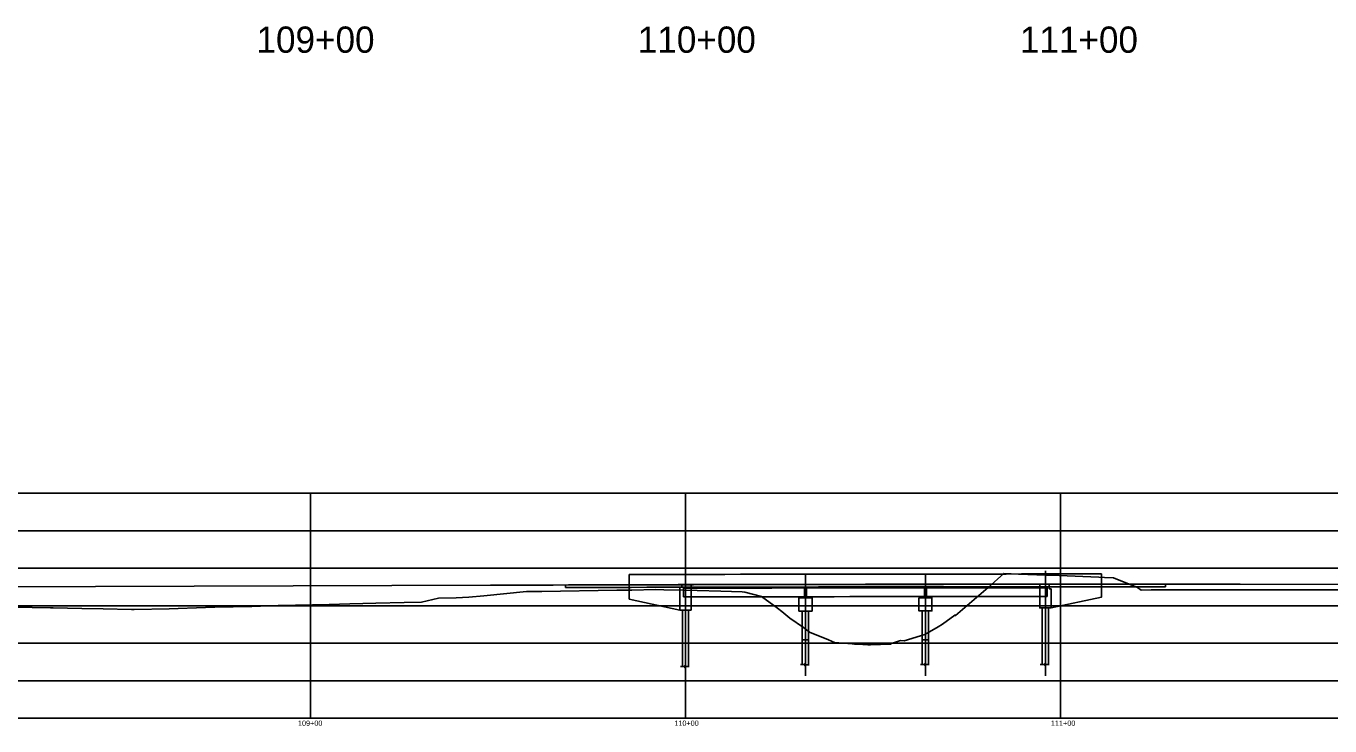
# Model space of a CAD drawing. Extents: x 1932071 to 1934815, y 598385 to 598883.
# Drawn here: x 1933216.8 to 1933564.6, y 598385.1 to 598571.7 of the extents above; entities that cross this region are included whole.
import ezdxf

# ---------------------------------------------------------------- set-up
doc = ezdxf.new("R2010")
doc.units = 0
for name, color, linetype in [('B_Centerline', 7, 'Continuous'), ('B_Concrete', 7, 'Continuous'), ('B_Pr_Abut_Wingwall', 7, 'Continuous'), ('B_Pr_Beam_Line', 7, 'Continuous'), ('B_Pr_Cap_Beams', 7, 'Continuous'), ('B_Pr_Columns', 7, 'Continuous'), ('B_Pr_Deck', 7, 'Continuous'), ('B_Pr_Rail', 7, 'Continuous'), ('BR_Pr_Cap_Beams', 7, 'Continuous'), ('Default', 7, 'Continuous'), ('R_Axis', 7, 'Continuous'), ('R_Axis Annot', 7, 'Continuous'), ('R_Exist Surface', 7, 'Continuous'), ('R_Grid', 7, 'Continuous'), ('R_Vert Alg', 7, 'Continuous'), ('R_Vert Alg Annot', 7, 'Continuous')]:
    doc.layers.add(name, color=color, linetype=linetype)

msp = doc.modelspace()

# ---------------------------------------------------------------- linework, layer by layer
at = {"layer": 'B_Centerline'}
for p, q in [((1933392.67, 598398.48), (1933392.67, 598425.77)), ((1933392.67, 598398.48), (1933392.67, 598425.77)), ((1933424.67, 598398.48), (1933424.67, 598425.77)), ((1933424.67, 598398.48), (1933424.67, 598425.77)), ((1933456.67, 598398.48), (1933456.67, 598425.77)), ((1933456.67, 598398.48), (1933456.67, 598425.77)), ((1933488.67, 598398.48), (1933488.67, 598425.77)), ((1933488.67, 598398.48), (1933488.67, 598425.77))]:
    msp.add_line(p, q, dxfattribs=at)
at = {"layer": 'B_Concrete'}
for p, q in [((1933377.67, 598422.74), (1933377.67, 598425.49)), ((1933377.67, 598422.74), (1933377.67, 598425.49)), ((1933503.67, 598422.89), (1933503.67, 598425.64)), ((1933503.67, 598422.89), (1933503.67, 598425.64)), ((1933520.67, 598422.22), (1933520.67, 598422.89)), ((1933520.67, 598422.22), (1933520.67, 598422.89)), ((1933360.67, 598422.03), (1933360.67, 598422.7)), ((1933360.67, 598422.03), (1933360.67, 598422.7))]:
    msp.add_line(p, q, dxfattribs=at)
for points in [[(1933377.67, 598425.49), (1933382.33, 598425.5), (1933386.5, 598425.51), (1933390.67, 598425.52), (1933394.83, 598425.53), (1933399, 598425.54), (1933403.17, 598425.54), (1933407.33, 598425.55), (1933411.5, 598425.56), (1933415.67, 598425.57), (1933419.83, 598425.57), (1933424, 598425.58), (1933428.17, 598425.58), (1933432.33, 598425.59), (1933436.5, 598425.6), (1933444.83, 598425.61), (1933449, 598425.61), (1933453.17, 598425.61), (1933457.33, 598425.62), (1933461.5, 598425.62), (1933465.67, 598425.63), (1933469.83, 598425.63), (1933474, 598425.63), (1933478.17, 598425.63), (1933482.33, 598425.64), (1933486.5, 598425.64), (1933490.67, 598425.64), (1933494.83, 598425.64), (1933499, 598425.64), (1933503.67, 598425.64)], [(1933377.67, 598425.49), (1933382.33, 598425.5), (1933386.5, 598425.51), (1933390.67, 598425.52), (1933394.83, 598425.53), (1933399, 598425.54), (1933403.17, 598425.54), (1933407.33, 598425.55), (1933411.5, 598425.56), (1933415.67, 598425.57), (1933419.83, 598425.57), (1933424, 598425.58), (1933428.17, 598425.58), (1933432.33, 598425.59), (1933436.5, 598425.6), (1933444.83, 598425.61), (1933449, 598425.61), (1933453.17, 598425.61), (1933457.33, 598425.62), (1933461.5, 598425.62), (1933465.67, 598425.63), (1933469.83, 598425.63), (1933474, 598425.63), (1933478.17, 598425.63), (1933482.33, 598425.64), (1933486.5, 598425.64), (1933490.67, 598425.64), (1933494.83, 598425.64), (1933499, 598425.64), (1933503.67, 598425.64)], [(1933360.67, 598422.03), (1933361.5, 598422.03), (1933365.67, 598422.04), (1933369.83, 598422.05), (1933374, 598422.06), (1933378.17, 598422.07), (1933382.33, 598422.08), (1933386.5, 598422.09), (1933390.67, 598422.1), (1933394.83, 598422.11), (1933399, 598422.12), (1933403.17, 598422.13), (1933407.33, 598422.13), (1933411.5, 598422.14), (1933415.67, 598422.15), (1933419.83, 598422.16), (1933424, 598422.16), (1933428.17, 598422.17), (1933432.33, 598422.17), (1933436.5, 598422.18), (1933444.83, 598422.19), (1933449, 598422.19), (1933453.17, 598422.2), (1933457.33, 598422.2), (1933461.5, 598422.21), (1933465.67, 598422.21), (1933469.83, 598422.21), (1933474, 598422.21), (1933478.17, 598422.22), (1933482.33, 598422.22), (1933486.5, 598422.22), (1933490.67, 598422.22), (1933494.83, 598422.22), (1933499, 598422.22), (1933503.17, 598422.22), (1933507.33, 598422.22), (1933511.5, 598422.22), (1933515.67, 598422.22), (1933519.83, 598422.22), (1933520.67, 598422.22)], [(1933360.67, 598422.03), (1933361.5, 598422.03), (1933365.67, 598422.04), (1933369.83, 598422.05), (1933374, 598422.06), (1933378.17, 598422.07), (1933382.33, 598422.08), (1933386.5, 598422.09), (1933390.67, 598422.1), (1933394.83, 598422.11), (1933399, 598422.12), (1933403.17, 598422.13), (1933407.33, 598422.13), (1933411.5, 598422.14), (1933415.67, 598422.15), (1933419.83, 598422.16), (1933424, 598422.16), (1933428.17, 598422.17), (1933432.33, 598422.17), (1933436.5, 598422.18), (1933444.83, 598422.19), (1933449, 598422.19), (1933453.17, 598422.2), (1933457.33, 598422.2), (1933461.5, 598422.21), (1933465.67, 598422.21), (1933469.83, 598422.21), (1933474, 598422.21), (1933478.17, 598422.22), (1933482.33, 598422.22), (1933486.5, 598422.22), (1933490.67, 598422.22), (1933494.83, 598422.22), (1933499, 598422.22), (1933503.17, 598422.22), (1933507.33, 598422.22), (1933511.5, 598422.22), (1933515.67, 598422.22), (1933519.83, 598422.22), (1933520.67, 598422.22)], [(1933392.17, 598421.85), (1933394.83, 598421.86), (1933399, 598421.87), (1933403.17, 598421.88), (1933407.33, 598421.88), (1933411.5, 598421.89), (1933415.67, 598421.9), (1933419.83, 598421.91), (1933424, 598421.91), (1933428.17, 598421.92), (1933432.33, 598421.92), (1933436.5, 598421.93), (1933444.83, 598421.94), (1933449, 598421.94), (1933453.17, 598421.95), (1933457.33, 598421.95), (1933461.5, 598421.96), (1933465.67, 598421.96), (1933469.83, 598421.96), (1933474, 598421.96), (1933478.17, 598421.97), (1933482.33, 598421.97), (1933486.5, 598421.97), (1933489.17, 598421.97)], [(1933392.17, 598421.85), (1933394.83, 598421.86), (1933399, 598421.87), (1933403.17, 598421.88), (1933407.33, 598421.88), (1933411.5, 598421.89), (1933415.67, 598421.9), (1933419.83, 598421.91), (1933424, 598421.91), (1933428.17, 598421.92), (1933432.33, 598421.92), (1933436.5, 598421.93), (1933444.83, 598421.94), (1933449, 598421.94), (1933453.17, 598421.95), (1933457.33, 598421.95), (1933461.5, 598421.96), (1933465.67, 598421.96), (1933469.83, 598421.96), (1933474, 598421.96), (1933478.17, 598421.97), (1933482.33, 598421.97), (1933486.5, 598421.97), (1933489.17, 598421.97)], [(1933392.17, 598419.52), (1933394.83, 598419.53), (1933399, 598419.54), (1933403.17, 598419.54), (1933407.33, 598419.55), (1933411.5, 598419.56), (1933415.67, 598419.57), (1933419.83, 598419.57), (1933424, 598419.58), (1933428.17, 598419.58), (1933432.33, 598419.59), (1933436.5, 598419.6), (1933444.83, 598419.61), (1933449, 598419.61), (1933453.17, 598419.61), (1933457.33, 598419.62), (1933461.5, 598419.62), (1933465.67, 598419.63), (1933469.83, 598419.63), (1933474, 598419.63), (1933478.17, 598419.63), (1933482.33, 598419.64), (1933486.5, 598419.64), (1933489.17, 598419.64)], [(1933392.17, 598419.52), (1933394.83, 598419.53), (1933399, 598419.54), (1933403.17, 598419.54), (1933407.33, 598419.55), (1933411.5, 598419.56), (1933415.67, 598419.57), (1933419.83, 598419.57), (1933424, 598419.58), (1933428.17, 598419.58), (1933432.33, 598419.59), (1933436.5, 598419.6), (1933444.83, 598419.61), (1933449, 598419.61), (1933453.17, 598419.61), (1933457.33, 598419.62), (1933461.5, 598419.62), (1933465.67, 598419.63), (1933469.83, 598419.63), (1933474, 598419.63), (1933478.17, 598419.63), (1933482.33, 598419.64), (1933486.5, 598419.64), (1933489.17, 598419.64)]]:
    msp.add_lwpolyline(points, dxfattribs=at)
at = {"layer": 'B_Pr_Abut_Wingwall'}
for p, q in [((1933489.67, 598422.89), (1933487.17, 598422.89)), ((1933487.17, 598416.57), (1933487.17, 598422.89)), ((1933489.67, 598422.89), (1933487.17, 598422.89)), ((1933487.17, 598416.57), (1933487.17, 598422.89)), ((1933489.67, 598422.89), (1933489.67, 598421.64)), ((1933489.67, 598422.89), (1933489.67, 598421.64)), ((1933489.67, 598421.64), (1933490.17, 598421.64)), ((1933489.67, 598421.64), (1933490.17, 598421.64)), ((1933490.17, 598416.57), (1933490.17, 598421.64)), ((1933490.17, 598416.57), (1933490.17, 598421.64))]:
    msp.add_line(p, q, dxfattribs=at)
msp.add_lwpolyline([(1933391.17, 598422.08), (1933391.17, 598416.01), (1933394.17, 598416.01), (1933394.17, 598422.8), (1933391.67, 598422.8), (1933391.67, 598422.08)], close=True, dxfattribs=at)
msp.add_lwpolyline([(1933391.17, 598422.08), (1933391.17, 598416.01), (1933394.17, 598416.01), (1933394.17, 598422.8), (1933391.67, 598422.8), (1933391.67, 598422.08)], close=True, dxfattribs=at)
for points in [[(1933391.17, 598416.01), (1933394.17, 598416.01)], [(1933391.17, 598416.01), (1933394.17, 598416.01), (1933394.17, 598416.01)], [(1933391.17, 598416.01), (1933394.17, 598416.01), (1933394.17, 598416.01)], [(1933391.17, 598416.01), (1933394.17, 598416.01)], [(1933391.17, 598416.01), (1933394.17, 598416.01), (1933394.17, 598416.01)], [(1933391.17, 598416.01), (1933394.17, 598416.01), (1933394.17, 598416.01)], [(1933487.17, 598416.57), (1933490.17, 598416.57), (1933490.17, 598416.57)], [(1933487.17, 598416.57), (1933490.17, 598416.57), (1933490.17, 598416.57)], [(1933490.17, 598416.57), (1933487.17, 598416.57), (1933487.17, 598416.57)], [(1933487.17, 598416.57), (1933490.17, 598416.57), (1933490.17, 598416.57)], [(1933487.17, 598416.57), (1933490.17, 598416.57), (1933490.17, 598416.57)], [(1933490.17, 598416.57), (1933487.17, 598416.57), (1933487.17, 598416.57)]]:
    msp.add_lwpolyline(points, dxfattribs=at)
at = {"layer": 'B_Pr_Beam_Line'}
for p, q in [((1933392.17, 598421.85), (1933392.17, 598419.52)), ((1933392.17, 598421.85), (1933392.17, 598419.52)), ((1933489.17, 598421.97), (1933489.17, 598419.64)), ((1933489.17, 598421.97), (1933489.17, 598419.64))]:
    msp.add_line(p, q, dxfattribs=at)
at = {"layer": 'B_Pr_Cap_Beams'}
for p, q in [((1933424.42, 598419.58), (1933424.42, 598421.91)), ((1933424.42, 598419.58), (1933424.42, 598421.91)), ((1933424.92, 598419.58), (1933424.92, 598421.91)), ((1933424.92, 598419.58), (1933424.92, 598421.91)), ((1933456.42, 598419.62), (1933456.42, 598421.95)), ((1933456.42, 598419.62), (1933456.42, 598421.95)), ((1933456.92, 598419.62), (1933456.92, 598421.95)), ((1933456.92, 598419.62), (1933456.92, 598421.95))]:
    msp.add_line(p, q, dxfattribs=at)
for points in [[(1933422.92, 598419.26), (1933426.42, 598419.26), (1933426.42, 598415.76), (1933422.92, 598415.76)], [(1933422.92, 598419.26), (1933426.42, 598419.26), (1933426.42, 598415.76), (1933422.92, 598415.76)], [(1933454.92, 598419.3), (1933458.42, 598419.3), (1933458.42, 598415.8), (1933454.92, 598415.8)], [(1933454.92, 598419.3), (1933458.42, 598419.3), (1933458.42, 598415.8), (1933454.92, 598415.8)]]:
    msp.add_lwpolyline(points, close=True, dxfattribs=at)
at = {"layer": 'B_Pr_Columns'}
for p, q in [((1933393.5, 598416.01), (1933391.83, 598416.01)), ((1933391.83, 598400.95), (1933391.83, 598416.01)), ((1933393.5, 598416.01), (1933391.83, 598416.01)), ((1933393.5, 598416.01), (1933391.83, 598416.01)), ((1933391.83, 598400.95), (1933391.83, 598416.01)), ((1933393.5, 598416.01), (1933391.83, 598416.01)), ((1933393.5, 598400.95), (1933393.5, 598416.01)), ((1933393.5, 598400.95), (1933393.5, 598416.01)), ((1933487.83, 598401.51), (1933487.83, 598416.57)), ((1933489.5, 598416.57), (1933487.83, 598416.57)), ((1933487.83, 598401.51), (1933487.83, 598416.57)), ((1933489.5, 598416.57), (1933487.83, 598416.57)), ((1933489.5, 598401.5), (1933489.5, 598416.57)), ((1933489.5, 598401.5), (1933489.5, 598416.57)), ((1933423.83, 598411.57), (1933423.83, 598415.76)), ((1933423.83, 598411.57), (1933423.83, 598415.76)), ((1933425.5, 598410.32), (1933425.5, 598415.76)), ((1933425.5, 598410.32), (1933425.5, 598415.76)), ((1933455.83, 598411.61), (1933455.83, 598415.8)), ((1933455.83, 598411.61), (1933455.83, 598415.8)), ((1933457.5, 598410.36), (1933457.5, 598415.8)), ((1933457.5, 598410.36), (1933457.5, 598415.8)), ((1933423.83, 598401.47), (1933423.83, 598411.57)), ((1933423.83, 598401.47), (1933423.83, 598411.57)), ((1933425.5, 598401.47), (1933425.5, 598410.32)), ((1933425.5, 598401.47), (1933425.5, 598410.32)), ((1933455.83, 598401.5), (1933455.83, 598411.61)), ((1933455.83, 598401.5), (1933455.83, 598411.61)), ((1933457.5, 598401.5), (1933457.5, 598410.36)), ((1933457.5, 598401.5), (1933457.5, 598410.36)), ((1933425.5, 598408.06), (1933423.83, 598408.06)), ((1933425.5, 598408.06), (1933423.83, 598408.06)), ((1933457.5, 598408.09), (1933455.83, 598408.09)), ((1933457.5, 598408.09), (1933455.83, 598408.09))]:
    msp.add_line(p, q, dxfattribs=at)
at = {"layer": 'B_Pr_Deck'}
for p, q in [((1933488.67, 598422.18), (1933488.67, 598422.89)), ((1933488.67, 598422.18), (1933488.67, 598422.89)), ((1933377.67, 598422.74), (1933392.67, 598422.8)), ((1933377.67, 598422.74), (1933392.67, 598422.8))]:
    msp.add_line(p, q, dxfattribs=at)
for points in [[(1933503.67, 598422.89), (1933503.67, 598419.5), (1933490.17, 598416.57)], [(1933503.67, 598422.89), (1933503.67, 598419.5), (1933490.17, 598416.57)], [(1933377.67, 598422.74), (1933377.67, 598418.94), (1933391.17, 598416.01)], [(1933377.67, 598422.74), (1933377.67, 598418.94), (1933391.17, 598416.01)]]:
    msp.add_lwpolyline(points, dxfattribs=at)
at = {"layer": 'B_Pr_Rail'}
for p, q in [((1933488.67, 598426.47), (1933488.67, 598422.97)), ((1933488.67, 598426.47), (1933488.67, 598422.97)), ((1933392.67, 598426.25), (1933392.67, 598422.88)), ((1933392.67, 598422.77), (1933392.67, 598426.25)), ((1933392.67, 598426.25), (1933392.67, 598422.88)), ((1933392.67, 598422.77), (1933392.67, 598426.25))]:
    msp.add_line(p, q, dxfattribs=at)
at = {"layer": 'BR_Pr_Cap_Beams'}
for p, q in [((1933423.33, 598419.26), (1933423.33, 598419.59)), ((1933423.33, 598419.26), (1933423.33, 598419.59)), ((1933424, 598419.26), (1933424, 598419.58)), ((1933424, 598419.26), (1933424, 598419.58)), ((1933425.33, 598419.26), (1933425.33, 598419.57)), ((1933425.33, 598419.26), (1933425.33, 598419.57)), ((1933426, 598419.26), (1933426, 598419.57)), ((1933426, 598419.26), (1933426, 598419.57)), ((1933455.33, 598419.3), (1933455.33, 598419.63)), ((1933455.33, 598419.3), (1933455.33, 598419.63)), ((1933456, 598419.3), (1933456, 598419.62)), ((1933456, 598419.3), (1933456, 598419.62)), ((1933457.33, 598419.3), (1933457.33, 598419.61)), ((1933457.33, 598419.3), (1933457.33, 598419.61)), ((1933458, 598419.3), (1933458, 598419.61)), ((1933458, 598419.3), (1933458, 598419.61))]:
    msp.add_line(p, q, dxfattribs=at)
at = {"layer": 'Default'}
for p, q in [((1933392.65, 598400.95), (1933393.67, 598400.95)), ((1933392.65, 598400.95), (1933393.67, 598400.95)), ((1933424.66, 598401.46), (1933425.68, 598401.46)), ((1933424.66, 598401.46), (1933425.68, 598401.46)), ((1933456.66, 598401.5), (1933457.68, 598401.5)), ((1933456.66, 598401.5), (1933457.68, 598401.5)), ((1933488.65, 598401.5), (1933489.67, 598401.5)), ((1933488.65, 598401.5), (1933489.67, 598401.5))]:
    msp.add_line(p, q, dxfattribs=at)
for points in [[(1933391.32, 598400.95), (1933392.39, 598400.95), (1933392.58, 598401.23), (1933392.45, 598400.69), (1933392.65, 598400.95)], [(1933391.32, 598400.95), (1933392.39, 598400.95), (1933392.58, 598401.23), (1933392.45, 598400.69), (1933392.65, 598400.95)], [(1933423.33, 598401.47), (1933424.4, 598401.47), (1933424.59, 598401.74), (1933424.46, 598401.21), (1933424.66, 598401.46)], [(1933423.33, 598401.47), (1933424.4, 598401.47), (1933424.59, 598401.74), (1933424.46, 598401.21), (1933424.66, 598401.46)], [(1933455.33, 598401.51), (1933456.4, 598401.51), (1933456.59, 598401.78), (1933456.46, 598401.25), (1933456.66, 598401.5)], [(1933455.33, 598401.51), (1933456.4, 598401.51), (1933456.59, 598401.78), (1933456.46, 598401.25), (1933456.66, 598401.5)], [(1933487.32, 598401.51), (1933488.39, 598401.51), (1933488.58, 598401.78), (1933488.45, 598401.25), (1933488.65, 598401.5)], [(1933487.32, 598401.51), (1933488.39, 598401.51), (1933488.58, 598401.78), (1933488.45, 598401.25), (1933488.65, 598401.5)]]:
    msp.add_lwpolyline(points, dxfattribs=at)
at = {"layer": 'R_Axis'}
msp.add_line((1932092.67, 598387.17), (1934792.67, 598387.17), dxfattribs=at)
at = {"layer": 'R_Exist Surface'}
msp.add_lwpolyline([(1933209.27, 598416.92), (1933218.42, 598416.71), (1933223.26, 598416.63), (1933224.03, 598416.61), (1933231.67, 598416.42), (1933237.36, 598416.32), (1933244.9, 598416.14), (1933245.57, 598416.15), (1933254.98, 598416.37), (1933264.62, 598416.71), (1933267.1, 598416.77), (1933277.01, 598416.99), (1933283.98, 598417.21), (1933288.63, 598417.31), (1933297.63, 598417.51), (1933303.17, 598417.68), (1933310.06, 598417.83), (1933317.66, 598418.01), (1933322.27, 598418.15), (1933326.77, 598419.15), (1933331.49, 598419.32), (1933334.89, 598419.44), (1933338.88, 598419.83), (1933350.28, 598420.99), (1933351.14, 598421), (1933352.91, 598420.99), (1933354.36, 598420.98), (1933374.34, 598421.3), (1933375.56, 598421.32), (1933378.34, 598421.36), (1933384.67, 598421.5), (1933386.88, 598421.41), (1933391.97, 598421.33), (1933395.77, 598421.22), (1933402.09, 598421.04), (1933407.81, 598420.89), (1933408.51, 598420.78), (1933412.96, 598419.61), (1933417.19, 598416.5), (1933418.39, 598415.62), (1933420.5, 598413.86), (1933424.14, 598411.36), (1933425.79, 598410.1), (1933430.81, 598408.06), (1933432.42, 598407.37), (1933437.09, 598407.01), (1933437.74, 598406.97), (1933438.26, 598406.95), (1933438.62, 598406.93), (1933441.31, 598406.79), (1933442, 598406.77), (1933447.35, 598406.97), (1933447.63, 598407.1), (1933450, 598407.9), (1933450.99, 598407.85), (1933456.48, 598409.47), (1933460.05, 598411.59), (1933461.23, 598412.3), (1933464.55, 598414.68), (1933464.65, 598414.55), (1933473.44, 598422.07), (1933477.55, 598425.8), (1933481.47, 598425.63), (1933488.92, 598425.31), (1933492.38, 598425.23), (1933502.9, 598424.75), (1933504.48, 598424.68), (1933506.8, 598424.62), (1933513.21, 598422), (1933514.19, 598421.32), (1933516.88, 598421.37), (1933524.33, 598421.38), (1933535.15, 598421.4), (1933537.68, 598421.4), (1933545.75, 598421.39), (1933558.49, 598421.38), (1933559.98, 598421.38), (1933561.32, 598421.39), (1933567.18, 598421.38)], dxfattribs=at)
at = {"layer": 'R_Grid'}
for p, q in [((1932092.67, 598447.17), (1934792.67, 598447.17)), ((1932092.67, 598447.17), (1934792.67, 598447.17)), ((1933292.67, 598387.17), (1933292.67, 598447.17)), ((1933392.67, 598387.17), (1933392.67, 598447.17)), ((1933492.67, 598387.17), (1933492.67, 598447.17)), ((1932092.67, 598437.17), (1934792.67, 598437.17)), ((1932092.67, 598427.17), (1934792.67, 598427.17)), ((1932092.67, 598417.17), (1934792.67, 598417.17)), ((1932092.67, 598407.17), (1934792.67, 598407.17)), ((1932092.67, 598397.17), (1934792.67, 598397.17))]:
    msp.add_line(p, q, dxfattribs=at)
at = {"layer": 'R_Vert Alg'}
for p, q in [((1933390.67, 598422.79), (1933440.67, 598422.94)), ((1933390.67, 598422.79), (1933440.67, 598422.94)), ((1933390.67, 598422.79), (1933440.67, 598422.94)), ((1933440.67, 598422.94), (1933490.67, 598422.91)), ((1933440.67, 598422.94), (1933490.67, 598422.91)), ((1933440.67, 598422.94), (1933490.67, 598422.91)), ((1933540.67, 598422.88), (1934265.61, 598422.45)), ((1933156.67, 598422.09), (1933340.67, 598422.64))]:
    msp.add_line(p, q, dxfattribs=at)
msp.add_lwpolyline([(1933340.67, 598422.64), (1933344.83, 598422.65), (1933349, 598422.67), (1933353.17, 598422.68), (1933357.33, 598422.69), (1933361.5, 598422.7), (1933365.67, 598422.71), (1933369.83, 598422.72), (1933374, 598422.73), (1933378.17, 598422.74), (1933382.33, 598422.75), (1933386.5, 598422.76), (1933390.67, 598422.77), (1933394.83, 598422.78), (1933399, 598422.79), (1933403.17, 598422.79), (1933407.33, 598422.8), (1933411.5, 598422.81), (1933415.67, 598422.82), (1933419.83, 598422.82), (1933424, 598422.83), (1933428.17, 598422.83), (1933432.33, 598422.84), (1933436.5, 598422.85), (1933444.83, 598422.86), (1933449, 598422.86), (1933453.17, 598422.86), (1933457.33, 598422.87), (1933461.5, 598422.87), (1933465.67, 598422.88), (1933469.83, 598422.88), (1933474, 598422.88), (1933478.17, 598422.88), (1933482.33, 598422.89), (1933486.5, 598422.89), (1933490.67, 598422.89), (1933494.83, 598422.89), (1933499, 598422.89), (1933503.17, 598422.89), (1933507.33, 598422.89), (1933511.5, 598422.89), (1933515.67, 598422.89), (1933519.83, 598422.89), (1933524, 598422.89), (1933528.17, 598422.89), (1933532.33, 598422.89), (1933536.5, 598422.88), (1933540.67, 598422.88)], dxfattribs=at)
msp.add_lwpolyline([(1933340.67, 598422.64), (1933344.83, 598422.65), (1933349, 598422.67), (1933353.17, 598422.68), (1933357.33, 598422.69), (1933361.5, 598422.7), (1933365.67, 598422.71), (1933369.83, 598422.72), (1933374, 598422.73), (1933378.17, 598422.74), (1933382.33, 598422.75), (1933386.5, 598422.76), (1933390.67, 598422.77), (1933394.83, 598422.78), (1933399, 598422.79), (1933403.17, 598422.79), (1933407.33, 598422.8), (1933411.5, 598422.81), (1933415.67, 598422.82), (1933419.83, 598422.82), (1933424, 598422.83), (1933428.17, 598422.83), (1933432.33, 598422.84), (1933436.5, 598422.85), (1933444.83, 598422.86), (1933449, 598422.86), (1933453.17, 598422.86), (1933457.33, 598422.87), (1933461.5, 598422.87), (1933465.67, 598422.88), (1933469.83, 598422.88), (1933474, 598422.88), (1933478.17, 598422.88), (1933482.33, 598422.89), (1933486.5, 598422.89), (1933490.67, 598422.89), (1933494.83, 598422.89), (1933499, 598422.89), (1933503.17, 598422.89), (1933507.33, 598422.89), (1933511.5, 598422.89), (1933515.67, 598422.89), (1933519.83, 598422.89), (1933524, 598422.89), (1933528.17, 598422.89), (1933532.33, 598422.89), (1933536.5, 598422.88), (1933540.67, 598422.88)], dxfattribs=at)
at = {"layer": 'R_Vert Alg Annot'}
for p, q in [((1933392.67, 598428.77), (1933392.67, 598440.62)), ((1933392.67, 598422.77), (1933392.67, 598428.77)), ((1933392.67, 598422.77), (1933392.67, 598428.77))]:
    msp.add_line(p, q, dxfattribs=at)

# ---------------------------------------------------------------- texts
at = {"layer": 'R_Axis Annot'}
for s, height, p in [('109+00', 7, (1933278.23, 598564.55)), ('110+00', 7, (1933379.94, 598564.55)), ('111+00', 7, (1933481.87, 598564.55)), ('109+00', 1.4, (1933289.3, 598385.17)), ('110+00', 1.4, (1933389.7, 598385.17)), ('111+00', 1.4, (1933490.15, 598385.17))]:
    msp.add_text(s, height=height, dxfattribs=at).set_placement(p)

doc.saveas('drawing.dxf')
